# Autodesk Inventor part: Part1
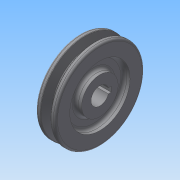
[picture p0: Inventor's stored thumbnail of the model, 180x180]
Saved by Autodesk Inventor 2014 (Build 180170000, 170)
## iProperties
Created: 2018-12
Part Number: Part1
Material: Generic
Document SubType Name: Modeling
Designer: hi
Density: 1 g/cm^3
Appearance: Default
Author: hi
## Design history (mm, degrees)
sketch "Sketch1"
  geometry: L1 (9.5, 0)-(-9.5, 0); L2 (2.178, -34.391)-(4.765, -42.355); L3 (-2.178, -34.391)-(-4.765, -42.355); L4 (1.226, -33.7)-(-1.226, -33.7); L5 (7.5, -42.7)-(5.241, -42.7); L6 (-5.241, -42.7)-(-7.5, -42.7); L7 (3.5, -17.5)-(3.5, -29); L8 (-3.5, -17.5)-(-3.5, -29); L9 (9.5, -29)-(3.5, -29); L10 (-3.5, -29)-(-9.5, -29); L11 (9.5, -17.5)-(3.5, -17.5); L12 (-3.5, -17.5)-(-9.5, -17.5); L13 (9.5, 0)-(9.5, -17.5); L14 (9.5, -29)-(9.5, -40.7); L15 (-9.5, 0)-(-9.5, -17.5); L16 (-9.5, -29)-(-9.5, -40.7); A1 r 2 centre (7.5, -40.7) between (7.5, -42.7) and (9.5, -40.7); A2 r 2 centre (-7.5, -40.7) between (-9.5, -40.7) and (-7.5, -42.7); A3 r 1 centre (1.226, -34.7) between (2.178, -34.391) and (1.226, -33.7); A4 r 1 centre (-1.226, -34.7) between (-1.226, -33.7) and (-2.178, -34.391); A5 r 0.5 centre (5.241, -42.2) between (4.765, -42.355) and (5.241, -42.7); A6 r 0.5 centre (-5.241, -42.2) between (-5.241, -42.7) and (-4.765, -42.355); 3 further points
  constraints: 32 end point, 14 tangent, 12 point on circle, 11 parallel, 6 centre point, 4 perpendicular, 3 equal radius, 2 point on line, 1 horizontal
  dimensions: "d0" = 19 distance of L1.start L1.end; "d7" = 2 radius of A1; "d8" = 1 radius of A3; "d9" = 0.5 radius of A5; "d10" = 3.5 distance from line of L7 point (0, 0); "d11" = 3.5 distance from line of L8 point (0, 0)
revolve "Revolution1" sketch "Sketch1" stored, may be unused: angle "d14" = 90 deg
fillet "Fillet1" dims "d15" = 3
sketch "Sketch2"
  geometry: L1 (-2.5, 8.124)-(-2.5, 10.8); L2 (2.5, 8.124)-(2.5, 10.8); L3 (-2.5, 10.8)-(2.5, 10.8); C1 r 17.5 at (0, 0) reference; C2 r 26 at (0, 0) reference; A1 r 8.5 centre (0, 0) between (-2.5, 8.124) and (2.5, 8.124)
  constraints: 6 end point, 2 point on circle, 1 centre point, 1 coincident
  dimensions: "d16" = 17 diameter of A1
extrude "Extrusion1" cut sketch "Sketch2" stored distance "d21" = 10; taper "d22" = 0 deg
body "Solid1"
other parameters: "d4" = 2.7, "d5" = 6.3, "d12" = 58, "d13" = 35
